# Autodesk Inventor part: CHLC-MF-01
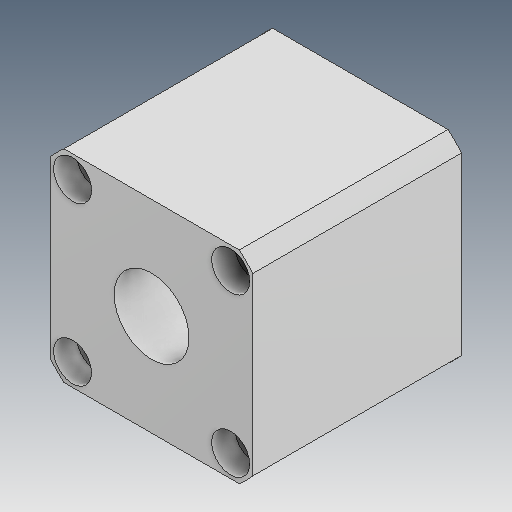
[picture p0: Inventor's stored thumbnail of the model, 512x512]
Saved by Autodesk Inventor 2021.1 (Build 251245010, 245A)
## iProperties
Created: 2021-05
Part Number: CHLC-MF-01
Material: Ogólny
Document SubType Name: Modeling
Designer: user
Density: 1 g/cm^3
Appearance: Domyślna
Author: user
Revision Number: ÈÎºÎ
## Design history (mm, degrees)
feature "ÊäÈë1"
node "Bryła1"
